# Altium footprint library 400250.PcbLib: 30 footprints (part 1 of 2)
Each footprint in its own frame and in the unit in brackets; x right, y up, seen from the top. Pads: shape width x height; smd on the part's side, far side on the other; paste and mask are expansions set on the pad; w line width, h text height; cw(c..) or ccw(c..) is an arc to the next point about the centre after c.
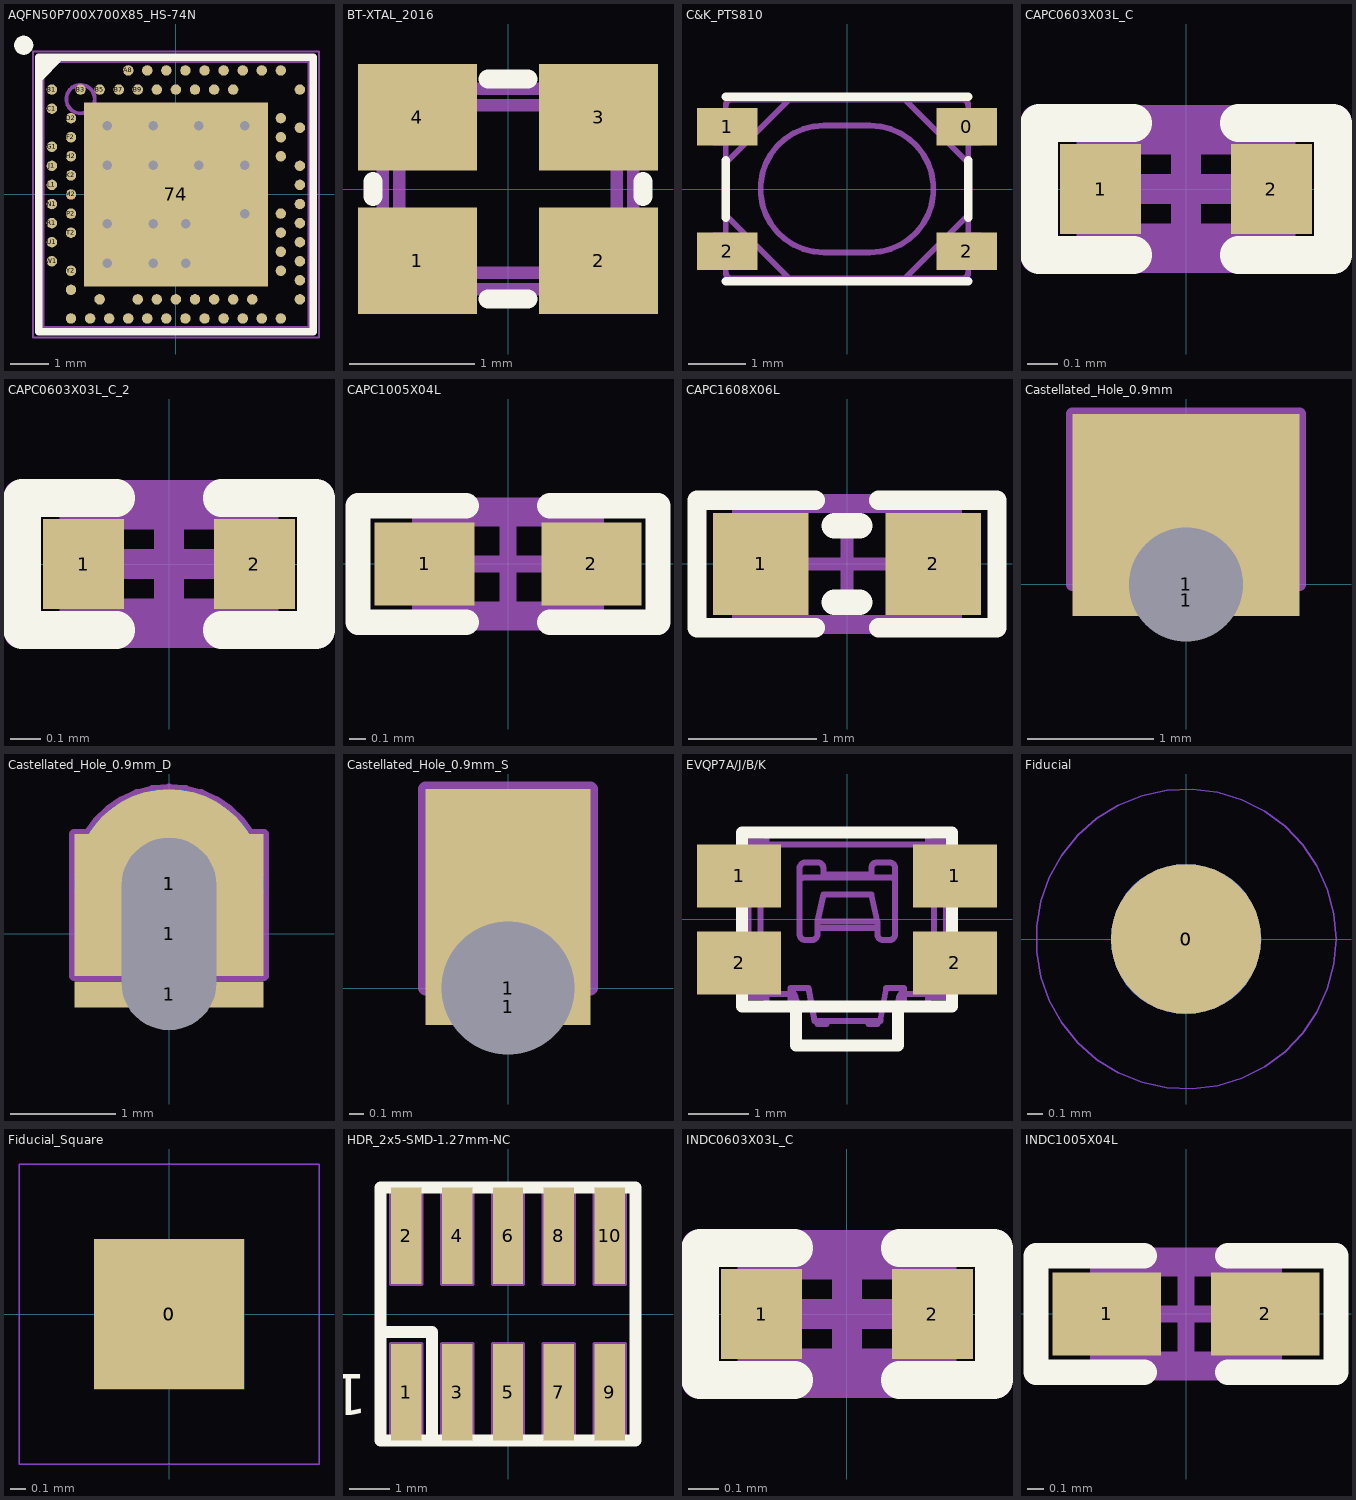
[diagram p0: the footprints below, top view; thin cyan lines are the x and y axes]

## AQFN50P700X700X85_HS-74N [mm] "AQFN, 73-Leads, Body 7.00x7.00mm, Pitch 0.50mm, Thermal Pad 4.95x4.95mm, IPC Medium Density"
height 0.85
pads (74):
  rect 4.83x4.83 smd mask+0.05: 74(0,0)
  round 0.275 smd paste+0.012 mask+0.05: A8(-1.25,3.25) A10(-0.75,3.25) A12(-0.25,3.25) A14(0.25,3.25) A16(0.75,3.25) A18(1.25,3.25) A20(1.75,3.25) A22(2.25,3.25) A23(2.75,3.25) AA24(3.25,-2.25) AB2(-2.75,-2.5) AC5(-2,-2.75) AC9(-1,-2.75) AC11(-0.5,-2.75) AC13(0,-2.75) AC15(0.5,-2.75) AC17(1,-2.75) AC19(1.5,-2.75) AC21(2,-2.75) AC24(3.25,-2.75) AD2(-2.75,-3.25) AD4(-2.25,-3.25) AD6(-1.75,-3.25) AD8(-1.25,-3.25) AD10(-0.75,-3.25) AD12(-0.25,-3.25) AD14(0.25,-3.25) AD16(0.75,-3.25) AD18(1.25,-3.25) AD20(1.75,-3.25) AD22(2.25,-3.25) AD23(2.75,-3.25) B1(-3.25,2.75) B3(-2.5,2.75) B5(-2,2.75) B7(-1.5,2.75) B9(-1,2.75) B11(-0.5,2.75) B13(0,2.75) B15(0.5,2.75) B17(1,2.75) B19(1.5,2.75) B24(3.25,2.75) C1(-3.25,2.25) D2(-2.75,2) D23(2.75,2) E24(3.25,1.75) F2(-2.75,1.5) F23(2.75,1.5) G1(-3.25,1.25) H2(-2.75,1) H23(2.75,1) J1(-3.25,0.75) J24(3.25,0.75) K2(-2.75,0.5) L1(-3.25,0.25) L24(3.25,0.25) M2(-2.75,0) N1(-3.25,-0.25) N24(3.25,-0.25) P2(-2.75,-0.5) P23(2.75,-0.5) R1(-3.25,-0.75) R24(3.25,-0.75) T2(-2.75,-1) T23(2.75,-1) U1(-3.25,-1.25) U24(3.25,-1.25) V23(2.75,-1.5) W1(-3.25,-1.75) W24(3.25,-1.75) Y2(-2.75,-2) Y23(2.75,-2)
via -1.8,1.8 diameter 0.5 hole 0.25
via -0.6,1.8 diameter 0.5 hole 0.25
via 0.6,1.8 diameter 0.5 hole 0.25
via 1.8,1.8 diameter 0.5 hole 0.25
via -1.8,0.762 diameter 0.5 hole 0.25
via -0.6,0.762 diameter 0.5 hole 0.25
via 0.6,0.762 diameter 0.5 hole 0.25
via 1.8,0.762 diameter 0.5 hole 0.25
via -1.8,-0.762 diameter 0.5 hole 0.25
via -0.6,-0.762 diameter 0.5 hole 0.25
via 0.254,-0.762 diameter 0.5 hole 0.25
via -1.8,-1.8 diameter 0.5 hole 0.25
via -0.6,-1.8 diameter 0.5 hole 0.25
via 0.254,-1.8 diameter 0.5 hole 0.25
via 1.8,-0.508 diameter 0.5 hole 0.25
Top Overlay:
  circle w0.25: c-3.988,3.912 r0.125
  region: -3,3.5 -3.5,3 -3.5,3.5
  lines w0.2: -3.6,-3.6 -3.6,3.6 3.6,3.6 3.6,-3.6 -3.6,-3.6
Mechanical 7:
  circle w0.1: c-2.5,2.5 r0.373
  lines w0.1: -3.5,-3.5 3.5,-3.5 3.5,3.5 -3.5,3.5 -3.5,-3.5
  text ".Designator" at 0.305,0.076 h0.3
Mechanical 15:
  lines w0.05: -3.75,-3.75 -3.75,3.75 3.75,3.75 3.75,-3.75 -3.75,-3.75
  lines w0.1: -0.5,0 0.5,0 ; 0,-0.5 0,0.5
3D body "LGA88C25P25X25_700X700X85.step": height 0.85, standoff 0, extent -3.55,-3.55 3.55,3.55

## BT-XTAL_2016 [mm] "Crystal 2.0 x 1.6 mm"
height 0.5
pads (4):
  rect 0.95x0.85 smd: 1(-0.725,-0.575) 2(0.725,-0.575) 3(0.725,0.575) 4(-0.725,0.575)
Top Overlay:
  lines w0.152: -1.08,-0.06 -1.08,0.06 ; -0.16,-0.88 0.16,-0.88 ; -0.16,0.88 0.16,0.88 ; 1.08,-0.06 1.08,0.06
Mechanical 7:
  lines w0.1: -1,-0.7 cw(c-1,-0.8) -0.9,-0.8 0.9,-0.8 cw(c1,-0.8) 1,-0.7 1,0.7 cw(c1,0.8) 0.9,0.8 -0.9,0.8 cw(c-1,0.8) -1,0.7 -1,-0.7 ; -0.87,-0.57 ccw(c-0.77,-0.57) -0.77,-0.67 0.77,-0.67 ccw(c0.77,-0.57) 0.87,-0.57 0.87,0.57 ccw(c0.77,0.57) 0.77,0.67 -0.77,0.67 ccw(c-0.77,0.57) -0.87,0.57 -0.87,-0.57
  text ".Designator" at -0.7,-0.2 h0.38
3D body "User Library-GeyerElectronics_KX5.step": height 0.56, standoff 0, extent -1.05,-0.85 1.05,0.85
3D body: height 0.56, standoff 0.15, extent -0.7,-0.65 0.7,0.65

## C&K_PTS810 [mm] "Microminiature SMT Top Actuated"
height 2.5
pads (4):
  rect 1.05x0.65 smd: 0(2.075,1.075) 1(-2.075,1.075) 2(-2.075,-1.075) 2(2.075,-1.075)
Top Overlay:
  lines w0.15: -2.1,-1.6 2.1,-1.6 ; -2.1,-0.5 -2.1,0.5 ; -2.1,1.6 2.1,1.6 ; 2.1,-0.5 2.1,0.5
Mechanical 7:
  lines w0.1: -2.1,-1.35 -2.3,-1.35 -2.3,-0.8 -2.1,-0.8 ; -2.1,-0.45 -1,-1.55 ; -2.1,0.45 -1,1.55 ; -2.1,0.8 -2.3,0.8 -2.3,1.35 -2.1,1.35 ; 1,-1.55 2.1,-0.45 ; 1,1.55 2.1,0.45 ; 2.1,-1.35 2.3,-1.35 2.3,-0.8 2.1,-0.8 ; 2.1,0.8 2.3,0.8 2.3,1.35 2.1,1.35 ; -2.1,-1.45 ccw(c-2,-1.45) -2,-1.55 2,-1.55 ccw(c2,-1.45) 2.1,-1.45 2.1,1.45 ccw(c2,1.45) 2,1.55 -2,1.55 ccw(c-2,1.45) -2.1,1.45 -2.1,-1.45 ; -0.4,-1.1 cw(c-0.4,0) -0.4,1.1 0.4,1.1 cw(c0.4,0) 0.4,-1.1 -0.4,-1.1
  text ".Designator" at -0.381,-0.152 h0.3
3D body "Y97LT25BADBFP_-PTS810 SJ 250 SMTR.stp": height 2.5, standoff 0, extent -2.287,-1.6 2.288,1.6

## CAPC0603X03L_C [mm] "Chip Capacitor, 2-Leads, Body 0.6x0.3mm, IPC High Density"
height 0.33
pads (2):
  rect 0.27x0.3 smd: 1(-0.285,0) 2(0.285,0)
Top Overlay:
  lines w0.125: -0.175,-0.22 -0.49,-0.22 -0.49,0.22 -0.175,0.22 ; 0.175,-0.22 0.49,-0.22 0.49,0.22 0.175,0.22
Mechanical 7:
  lines w0.1: -0.315,-0.165 0.315,-0.165 0.315,0.165 -0.315,0.165 -0.315,-0.165
  text ".Designator" at 1.219,0.152 h0.3
Mechanical 15:
  lines w0.1: -0.165,0 0.165,0 ; 0,-0.165 0,0.165 ; -0.5,-0.23 0.5,-0.23 0.5,0.23 -0.5,0.23 -0.5,-0.23
3D body "User Library-0201(0603M) Cap.step": height 0.3, standoff -0.01, extent -0.305,-0.152 0.305,0.153

## CAPC0603X03L_C_2 [mm]
pads (2):
  rect 0.27x0.3 smd: 1(-0.285,0) 2(0.285,0)
Top Overlay:
  lines w0.125: -0.175,-0.22 -0.49,-0.22 -0.49,0.22 -0.175,0.22 ; 0.175,-0.22 0.49,-0.22 0.49,0.22 0.175,0.22
Mechanical 7:
  lines w0.1: -0.315,-0.165 -0.315,0.165 0.315,0.165 0.315,-0.165 -0.315,-0.165
  text ".Designator" at -1.27,-0.178 h0.3
Mechanical 15:
  lines w0.1: -0.165,0 0.165,0 ; 0,-0.165 0,0.165 ; -0.5,-0.23 -0.5,0.23 0.5,0.23 0.5,-0.23 -0.5,-0.23
3D body "User Library-0201(0603M) Cap.step": height 0.3, standoff -0.01, extent -0.305,-0.152 0.305,0.153

## CAPC1005X04L [mm] "Chip Capacitor, 2-Leads, Body 1.0x0.5mm, IPC High Density"
height 0.4
pads (2):
  rect 0.6x0.5 smd: 1(-0.5,0) 2(0.5,0)
Top Overlay:
  lines w0.152: -0.25,-0.35 -0.9,-0.35 -0.9,0.35 -0.25,0.35 ; 0.25,-0.35 0.9,-0.35 0.9,0.35 0.25,0.35
Mechanical 7:
  lines w0.1: -0.525,-0.275 0.525,-0.275 0.525,0.275 -0.525,0.275 -0.525,-0.275
  text ".Designator" at -0.406,-0.152 h0.3
Mechanical 15:
  lines w0.1: -0.275,0 0.275,0 ; 0,-0.275 0,0.275 ; -0.9,-0.35 -0.9,0.35 0.9,0.35 0.9,-0.35 -0.9,-0.35
3D body "User Library-0402(1005M) Cap.step": height 0.5, standoff -0.01, extent -0.508,-0.254 0.508,0.254

## CAPC1608X06L [mm] "Chip Capacitor, 2-Leads, Body 1.6x0.8mm, IPC High Density"
height 0.55
pads (2):
  rect 0.75x0.8 smd: 1(-0.675,0) 2(0.675,0)
Top Overlay:
  lines w0.152: -0.25,-0.5 -1.175,-0.5 -1.175,0.5 -0.25,0.5 ; 0.25,-0.5 1.175,-0.5 1.175,0.5 0.25,0.5
  lines w0.2: -0.1,-0.3 0.1,-0.3 ; -0.1,0.3 0.1,0.3
Mechanical 7:
  lines w0.1: -0.85,-0.45 0.85,-0.45 0.85,0.45 -0.85,0.45 -0.85,-0.45
  text ".Designator" at 0.392,0.152 h0.3
Mechanical 15:
  lines w0.1: -0.45,0 0.45,0 ; 0,-0.45 0,0.45 ; -1.175,-0.5 -1.175,0.5 1.175,0.5 1.175,-0.5 -1.175,-0.5
3D body "User Library-Chip Capacitor 0603.step": height 0.8, standoff 0, extent -0.8,-0.43 0.8,0.43

## Castellated_Hole_0.9mm [mm]
pads (2):
  rect 1.8x0.25 hole 0.25 square: 1(0,-0.126)
  rect 1.8x1.35 hole 0.9 copper offset 0,0.675: 1(0,0)
Mechanical 7:
  lines w0.1: -0.9,0 -0.9,1.35 0.9,1.35 0.9,0 0.45,0 ccw(c0,0) -0.45,0 -0.9,0
Mechanical 8:
  lines w0.1: -0.9,0 -0.45,0 cw(c0,0) 0.45,0 0.9,0 0.9,1.35 -0.9,1.35 -0.9,0

## Castellated_Hole_0.9mm_D [mm]
height 6
pads (4):
  rect 1.8x0.25 hole 0.25 square: 1(0,-0.576)
  rect 1.8x1.35 hole 0.9 slot 1.83 at 90 deg copper offset 0,0.275: 1(0,0)
  round 1.8 smd paste-5: 1(0,0.48)
  round 1.8 smd far side paste-5: 1(0,0.48)
Mechanical 7:
  lines w0.1: -0.77,0.95 -0.9,0.95 -0.9,-0.4 -0.45,-0.4 -0.45,0.465 cw(c0,0.465) 0.45,0.465 0.45,-0.4 0.9,-0.4 0.9,0.95 0.77,0.95 ; -0.768,0.949 cw(c0,0.48) 0.768,0.949
Mechanical 8:
  lines w0.1: -0.77,0.95 -0.9,0.95 -0.9,-0.4 -0.45,-0.4 -0.45,0.465 cw(c0,0.465) 0.45,0.465 0.45,-0.4 0.9,-0.4 0.9,0.95 0.77,0.95 ; -0.768,0.949 cw(c0,0.48) 0.768,0.949

## Castellated_Hole_0.9mm_S [mm]
height 9.5
pads (2):
  rect 1.118x0.25 hole 0.25 square: 1(0,-0.126)
  rect 1.118x1.35 hole 0.9 copper offset 0,0.675: 1(0,0)
Mechanical 7:
  lines w0.1: -0.559,0 -0.559,1.35 0.559,1.35 0.559,0 0.45,0 ccw(c0,0) -0.45,0 -0.559,0
Mechanical 8:
  lines w0.1: -0.559,0 -0.45,0 cw(c0,0) 0.45,0 0.559,0 0.559,1.35 -0.559,1.35 -0.559,0

## EVQP7A/J/B/K [mm] "Subminiature Side Actuated Tact Switch for SMT"
height 1.35
pads (4):
  rect 1.4x1.05 smd: 1(-1.8,0.725) 1(1.8,0.725) 2(-1.8,-0.725) 2(1.8,-0.725)
Top Overlay:
  lines w0.2: -0.85,-1.45 -0.85,-2.1 0.85,-2.1 0.85,-1.45 ; -1.75,-1.45 -1.75,1.45 1.75,1.45 1.75,-1.45 -1.75,-1.45
Mechanical 7:
  drawing of 222 lines, arcs and shapes, not listed
3D body "User Library-EVQP7-JA-01P.step": height 1.35, standoff 0, extent -2.35,-2.1 2.35,1.45

## Fiducial [mm] "Fiducial Mark"
height 0.35
pads (2):
  round 1 smd paste+0 mask+0.5: 0(0,0)
  round 1 smd far side paste+0 mask+0.5: 0(0,0)
Top Layer keep-out:
  circle w0.01: c0,0 r1
Bottom Layer keep-out:
  circle w0.01: c0,0 r1

## Fiducial_Square [mm] "Fiducial Mark"
pads (2):
  rect 1x1 smd paste-10 mask+0.5: 0(0,0)
  rect 1x1 smd far side paste-10 mask+0.5: 0(0,0)
Top Layer keep-out:
  lines w0.01: -1,-1 -1,1 1,1 1,-1 -1,-1
Bottom Layer keep-out:
  lines w0.01: -1,-1 1,-1 1,1 -1,1 -1,-1

## HDR_2x5-SMD-1.27mm-NC [mm] "SMT MICRO HEADER, (1,27) .050\""
height 4.68
pads (10):
  rect 0.76x2.4 smd: 1(-2.54,-1.95) 2(-2.54,1.95) 3(-1.27,-1.95) 4(-1.27,1.95) 5(0,-1.95) 6(0,1.95) 7(1.27,-1.95) 8(1.27,1.95) 9(2.54,-1.95) 10(2.54,1.95)
Top Overlay:
  lines w0.3: -3.175,-0.45 -1.9,-0.45 -1.9,-3.15 ; -3.175,-3.15 3.175,-3.15 3.175,3.15 -3.175,3.15 -3.175,-3.15
  text "1" at -3.505,-1.499 h1.02
Mechanical 7:
  lines w0.1: -3.175,-3.15 3.137,-3.15 3.137,3.15 -3.175,3.15 -3.175,-3.15 ; -2.92,-3.15 -2.16,-3.15 -2.16,-0.75 -2.92,-0.75 -2.92,-3.15 ; -2.92,0.75 -2.16,0.75 -2.16,3.15 -2.92,3.15 -2.92,0.75 ; -1.65,-3.15 -0.89,-3.15 -0.89,-0.75 -1.65,-0.75 -1.65,-3.15 ; -1.65,0.75 -0.89,0.75 -0.89,3.15 -1.65,3.15 -1.65,0.75 ; -0.38,-3.15 0.38,-3.15 0.38,-0.75 -0.38,-0.75 -0.38,-3.15 ; -0.38,0.75 -0.38,3.15 0.38,3.15 0.38,0.75 -0.38,0.75 ; 0.89,-3.15 1.65,-3.15 1.65,-0.75 0.89,-0.75 0.89,-3.15 ; 0.89,0.75 1.65,0.75 1.65,3.15 0.89,3.15 0.89,0.75 ; 2.16,-3.15 2.92,-3.15 2.92,-0.75 2.16,-0.75 2.16,-3.15 ; 2.16,0.75 2.92,0.75 2.92,3.15 2.16,3.15 2.16,0.75
  text ".Designator" at 0.254,0.178 h0.3

## INDC0603X03L_C [mm] "Chip Inductor, 2-Leads, Body 0.6x0.3mm, IPC High Density"
height 0.33
pads (2):
  rect 0.27x0.3 smd: 1(-0.285,0) 2(0.285,0)
Top Overlay:
  lines w0.125: -0.175,-0.22 -0.49,-0.22 -0.49,0.22 -0.175,0.22 ; 0.175,-0.22 0.49,-0.22 0.49,0.22 0.175,0.22
Mechanical 7:
  lines w0.1: -0.315,-0.165 0.315,-0.165 0.315,0.165 -0.315,0.165 -0.315,-0.165
  text ".Designator" at -0.457,0.152 h0.3
Mechanical 15:
  lines w0.1: -0.165,0 0.165,0 ; 0,-0.165 0,0.165 ; -0.5,-0.23 0.5,-0.23 0.5,0.23 -0.5,0.23 -0.5,-0.23
3D body "User Library-smt_inductor-0201.step": height 0.26, standoff -0.01, extent -0.31,-0.16 0.31,0.16

## INDC1005X04L [mm] "Chip Inductor, 2-Leads, Body 1.0x0.5mm, IPC High Density"
height 0.4
pads (2):
  rect 0.65x0.5 smd: 1(-0.475,0) 2(0.475,0)
Top Overlay:
  lines w0.152: -0.25,-0.35 -0.9,-0.35 -0.9,0.35 -0.25,0.35 ; 0.25,-0.35 0.9,-0.35 0.9,0.35 0.25,0.35
Mechanical 7:
  lines w0.1: -0.525,-0.275 -0.525,0.275 0.525,0.275 0.525,-0.275 -0.525,-0.275
  text ".Designator" at -0.229,-0.142 h0.3
Mechanical 15:
  lines w0.1: -0.275,0 0.275,0 ; 0,-0.275 0,0.275 ; -0.9,-0.35 -0.9,0.35 0.9,0.35 0.9,-0.35 -0.9,-0.35
3D body "User Library-Chip Inductor 0402.step": height 0.5, standoff 0, extent -0.5,-0.3 0.5,0.3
